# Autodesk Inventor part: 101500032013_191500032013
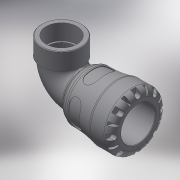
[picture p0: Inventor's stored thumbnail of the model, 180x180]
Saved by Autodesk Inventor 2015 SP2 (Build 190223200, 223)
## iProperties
Created: 2016-12
Part Number: 101500032013_191500032013
Material: Generic
Description: PLASSON 90° ELBOW WITH THREADED FEMALE OFFTAKE 32X1.1/4" SERIES 1
Document SubType Name: Modeling
Designer: KIM
Mass: 557.611 g
Surface Area: 990.043 cm^2
Volume: 557.611 cm^3
Density: 1 g/cm^3
Appearance: Default
Author: KIM
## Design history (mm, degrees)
derived "1015.ipt"
feature "Solid1::1015.ipt"
tag "TaggingFeature1"
body "Solid1"
other parameters: "d1" = 22.68, "d2" = 32, "d4" = 58, "d8" = 51.04, "d13" = 7.2, "d14" = 7.2, "d15" = 0, "d17" = 360 deg, "d19" = 8 deg, "d20" = 0.64, "d21" = 0.64, "d22" = 8 deg, "d24" = 0, "d26" = 360 deg, "d33" = 5.8, "d43" = 47.56, "d51" = 0.58, "d54" = 11.2, "d55" = 7.04, "d57" = 14.112, "d58" = 0, "d74" = 0, "d78" = 54, "d82" = 0.64, "d115" = 360 deg, "d207" = 90 deg, "d228" = 9.52, "d247" = 1.16, "d248" = 3.24, "d268" = 28.072, "d269" = 3.24, "d270" = 83, "d281" = 5.8428, "d294" = 38.952, "d295" = 24, "d296" = 26.4, "d297" = 35.0568, "d299" = 45.57384, "d300" = 35.0568, "d301" = 0, "d302" = 0, "d303" = 0.99308, "d306" = 0, "d307" = 9, "d308" = 8, "d310" = 3, "d_" = 32, "E_" = 58, "l_" = 54, "A_" = 83, "l_2" = 24, "Rp_" = 38.952, "d9" = 9, "d11" = 58, "d298" = 50.6376
